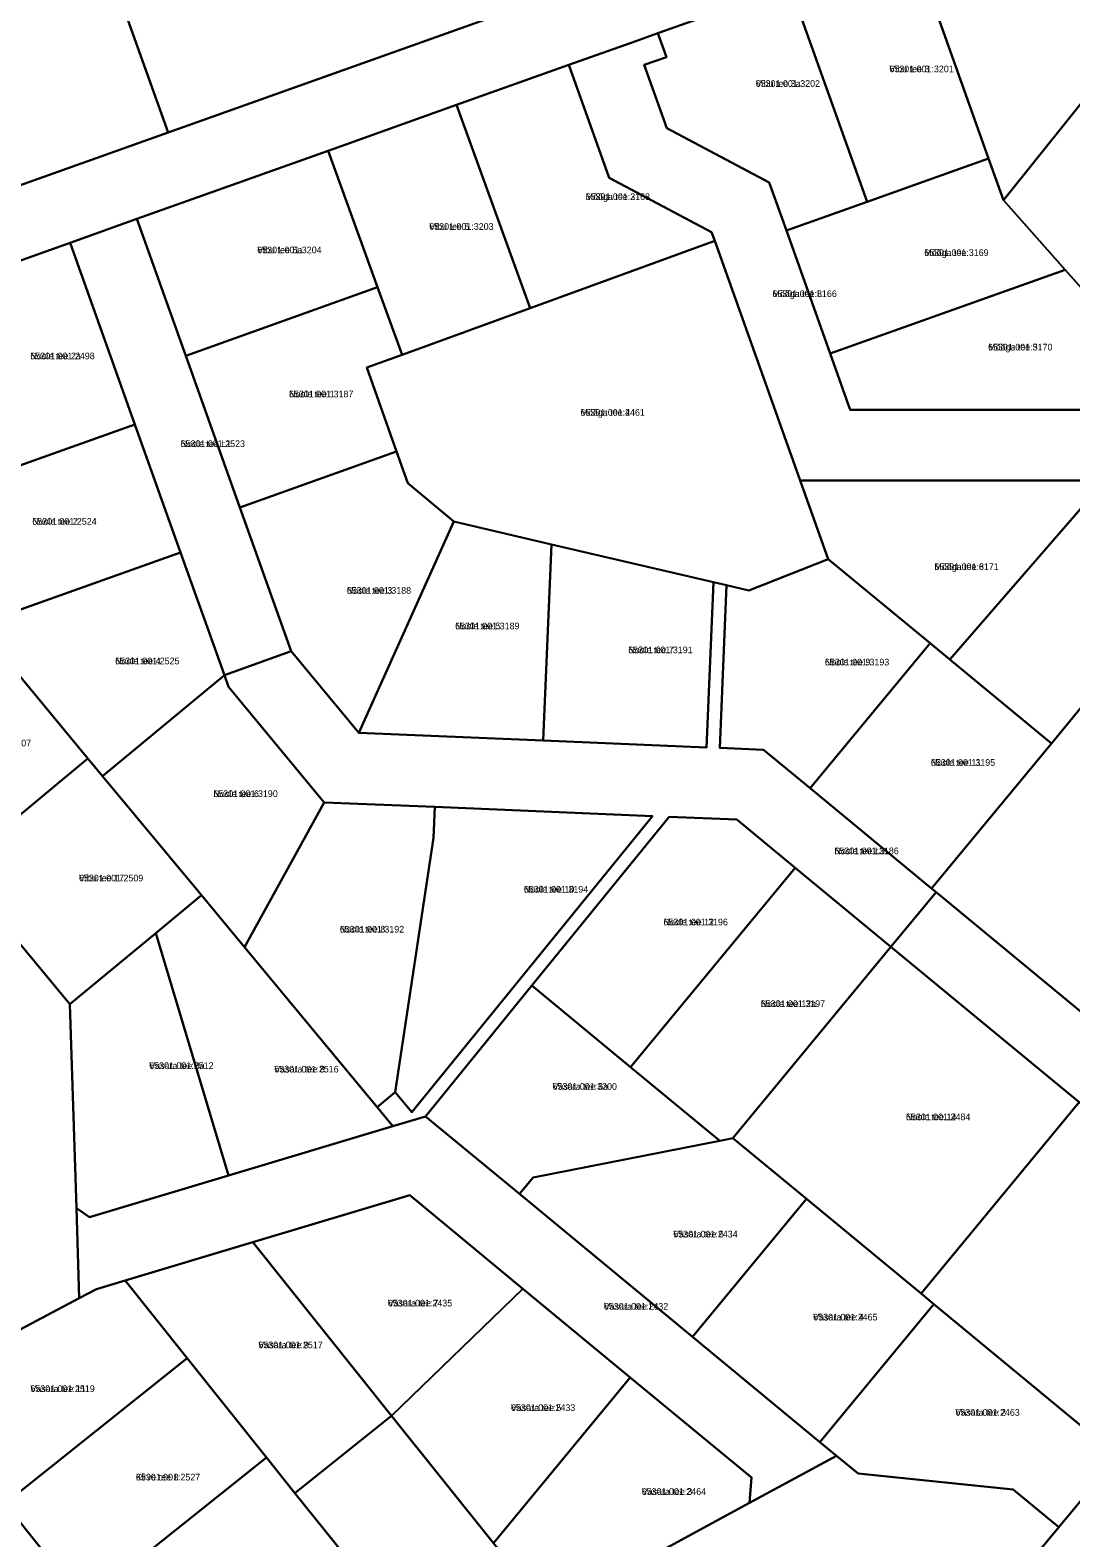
# Model space of a CAD drawing. Extents: x 543236 to 563717, y 6566033 to 6588992.
# Drawn here: x 546335.4 to 546570, y 6582727.8 to 6583067.8 of the extents above; entities that cross this region are included whole.
import ezdxf

# ---------------------------------------------------------------- set-up
doc = ezdxf.new("R2010")
doc.units = 0
for name, color, linetype in [('L_AADRESS', 7, 'Continuous'), ('PIIR', 7, 'Continuous'), ('TUNNUS', 7, 'Continuous')]:
    doc.layers.add(name, color=color, linetype=linetype)

msp = doc.modelspace()

# ---------------------------------------------------------------- linework, layer by layer
at = {"layer": 'PIIR'}
for points in [[(546592.18, 6583076.12), (546569.09, 6583101.29), (546579.76, 6583110.6), (546601.81, 6583088.17), (546654.4, 6583046.93), (546650.13, 6583042.2), (546634.72, 6583025.32), (546626.48, 6583016.25), (546596.15, 6582982.97), (546568.74, 6583013.76), (546554.83, 6583029.43)], [(546354.5, 6583078.41), (546379.75, 6583087.41), (546407.07, 6583097.15), (546433.62, 6583106.63), (546445.64, 6583072.93), (546366.52, 6583044.72)], [(546534.12, 6583087.49), (546566.53, 6583099.04), (546569.09, 6583101.29), (546592.18, 6583076.12), (546554.83, 6583029.43), (546551.45, 6583038.88)], [(546506.73, 6583077.72), (546534.12, 6583087.49), (546551.45, 6583038.88), (546524.06, 6583029.11)], [(546275.38, 6583050.2), (546297.81, 6583058.19), (546325.12, 6583067.92), (546352.44, 6583077.66), (546354.5, 6583078.41), (546366.52, 6583044.72), (546287.4, 6583016.51)], [(546476.92, 6583067.09), (546506.73, 6583077.72), (546524.06, 6583029.11), (546505.87, 6583022.63), (546502.02, 6583033.43), (546478.92, 6583045.71), (546473.85, 6583059.96), (546478.83, 6583061.73)], [(546456.84, 6583059.94), (546471.94, 6583065.32), (546476.92, 6583067.09), (546478.83, 6583061.73), (546473.85, 6583059.96), (546478.92, 6583045.71), (546502.02, 6583033.43), (546505.87, 6583022.63), (546515.78, 6582994.85), (546520.29, 6582982.2), (546583.47, 6582982.2), (546589.34, 6582977.35), (546609.88, 6582960.38), (546599.62, 6582948.1), (546577.72, 6582966.2), (546509.01, 6582966.2), (546489.73, 6583020.25), (546489.03, 6583022.22), (546465.95, 6583034.48)], [(546431.55, 6583050.92), (546456.84, 6583059.94), (546465.95, 6583034.48), (546489.03, 6583022.22), (546489.73, 6583020.25), (546448.16, 6583005.11)], [(546402.59, 6583040.59), (546431.55, 6583050.92), (546448.16, 6583005.11), (546419.27, 6582994.58), (546413.74, 6583009.83)], [(546359.49, 6583025.23), (546402.59, 6583040.59), (546413.74, 6583009.83), (546370.49, 6582994.37)], [(546505.87, 6583022.63), (546524.06, 6583029.11), (546551.45, 6583038.88), (546554.83, 6583029.43), (546568.74, 6583013.76), (546515.78, 6582994.85)], [(546344.42, 6583019.85), (546359.49, 6583025.23), (546370.49, 6582994.37), (546382.69, 6582960.16), (546394.26, 6582927.72), (546379.19, 6582922.34), (546369.33, 6582950), (546359.03, 6582978.88)], [(546311.88, 6583008.25), (546344.42, 6583019.85), (546359.03, 6582978.88), (546326.49, 6582967.28)], [(546411.32, 6582991.7), (546419.27, 6582994.58), (546448.16, 6583005.11), (546489.73, 6583020.25), (546509.01, 6582966.2), (546515.31, 6582948.52), (546497.41, 6582941.42), (546492.39, 6582942.6), (546489.42, 6582943.29), (546452.92, 6582951.83), (546430.89, 6582956.99), (546420.58, 6582965.63), (546418.03, 6582972.79)], [(546515.78, 6582994.85), (546568.74, 6583013.76), (546596.15, 6582982.97), (546589.34, 6582977.35), (546583.47, 6582982.2), (546520.29, 6582982.2)], [(546370.49, 6582994.37), (546413.74, 6583009.83), (546419.27, 6582994.58), (546411.32, 6582991.7), (546418.03, 6582972.79), (546382.69, 6582960.16)], [(546302.63, 6582958.77), (546326.49, 6582967.28), (546359.03, 6582978.88), (546369.33, 6582950), (546323.46, 6582933.65)], [(546382.69, 6582960.16), (546418.03, 6582972.79), (546420.58, 6582965.63), (546430.89, 6582956.99), (546409.5, 6582909.34), (546394.26, 6582927.72)], [(546509.01, 6582966.2), (546577.72, 6582966.2), (546542.69, 6582925.9), (546538.28, 6582929.54), (546515.31, 6582948.52)], [(546577.72, 6582966.2), (546599.62, 6582948.1), (546596.05, 6582943.78), (546572.2, 6582914.91), (546565.62, 6582906.95), (546542.69, 6582925.9)], [(546430.89, 6582956.99), (546452.92, 6582951.83), (546451.07, 6582907.6), (546409.5, 6582909.34)], [(546323.46, 6582933.65), (546369.33, 6582950), (546379.19, 6582922.34), (546351.73, 6582899.57), (546348.45, 6582903.53)], [(546452.92, 6582951.83), (546489.42, 6582943.29), (546487.86, 6582906.06), (546451.07, 6582907.6)], [(546492.39, 6582942.6), (546497.41, 6582941.42), (546515.31, 6582948.52), (546538.28, 6582929.54), (546511.26, 6582896.84), (546500.75, 6582905.52), (546490.85, 6582905.94)], [(546379.19, 6582922.34), (546394.26, 6582927.72), (546409.5, 6582909.34), (546451.07, 6582907.6), (546487.86, 6582906.06), (546489.42, 6582943.29), (546492.39, 6582942.6), (546490.85, 6582905.94), (546500.75, 6582905.52), (546511.26, 6582896.84), (546538.61, 6582874.25), (546539.65, 6582873.39), (546529.46, 6582861.05), (546507.86, 6582878.9), (546494.7, 6582889.76), (546479.46, 6582890.4), (546448.52, 6582852.34), (546424.54, 6582822.84), (546417.19, 6582820.63), (546413.64, 6582824.92), (546417.67, 6582828.31), (546421.45, 6582823.8), (546475.72, 6582890.56), (546426.67, 6582892.61), (546401.72, 6582893.66), (546380.14, 6582919.68)], [(546293.83, 6582909.07), (546323.46, 6582933.65), (546348.45, 6582903.53), (546318.81, 6582878.95)], [(546538.28, 6582929.54), (546542.69, 6582925.9), (546565.62, 6582906.95), (546538.61, 6582874.25), (546511.26, 6582896.84)], [(546351.73, 6582899.57), (546379.19, 6582922.34), (546380.14, 6582919.68), (546401.72, 6582893.66), (546383.74, 6582860.97), (546374.02, 6582872.69)], [(546572.2, 6582914.91), (546603.15, 6582889.34), (546616.11, 6582878.64), (546582.51, 6582837.98), (546582.05, 6582838.36), (546539.65, 6582873.39), (546538.61, 6582874.25), (546565.62, 6582906.95)], [(546318.81, 6582878.95), (546348.45, 6582903.53), (546351.73, 6582899.57), (546374.02, 6582872.69), (546363.72, 6582864.16), (546344.38, 6582848.12)], [(546401.72, 6582893.66), (546426.67, 6582892.61), (546426.37, 6582885.62), (546417.67, 6582828.31), (546413.64, 6582824.92), (546383.74, 6582860.97)], [(546426.67, 6582892.61), (546475.72, 6582890.56), (546421.45, 6582823.8), (546417.67, 6582828.31), (546426.37, 6582885.62)], [(546479.46, 6582890.4), (546494.7, 6582889.76), (546507.86, 6582878.9), (546470.74, 6582833.97), (546448.52, 6582852.34)], [(546507.86, 6582878.9), (546529.46, 6582861.05), (546493.83, 6582817.93), (546490.85, 6582817.34), (546470.74, 6582833.97)], [(546363.72, 6582864.16), (546374.02, 6582872.69), (546383.74, 6582860.97), (546413.64, 6582824.92), (546417.19, 6582820.63), (546380.14, 6582809.51)], [(546529.46, 6582861.05), (546539.65, 6582873.39), (546582.05, 6582838.36), (546626.94, 6582801.27), (546616.68, 6582788.99), (546571.86, 6582826.02)], [(546344.38, 6582848.12), (546363.72, 6582864.16), (546380.14, 6582809.51), (546348.79, 6582800.09), (546345.83, 6582802.18)], [(546493.83, 6582817.93), (546529.46, 6582861.05), (546571.86, 6582826.02), (546536.23, 6582782.9), (546510.39, 6582804.25)], [(546448.52, 6582852.34), (546470.74, 6582833.97), (546490.85, 6582817.34), (546448.79, 6582809.06), (546445.72, 6582805.34), (546424.54, 6582822.84)], [(546536.23, 6582782.9), (546571.86, 6582826.02), (546616.68, 6582788.99), (546580.62, 6582746.23), (546539.15, 6582780.49)], [(546345.83, 6582802.18), (546348.79, 6582800.09), (546380.14, 6582809.51), (546417.19, 6582820.63), (546424.54, 6582822.84), (546445.72, 6582805.34), (546484.69, 6582773.14), (546513.45, 6582749.39), (546517.18, 6582746.3), (546497.6, 6582735.66), (546498.02, 6582741.38), (546470.69, 6582763.95), (546446.44, 6582783.99), (546420.97, 6582805.04), (546385.64, 6582794.45), (546356.83, 6582785.82), (546350.39, 6582783.89), (546346.48, 6582781.82)], [(546445.72, 6582805.34), (546448.79, 6582809.06), (546490.85, 6582817.34), (546493.83, 6582817.93), (546510.39, 6582804.25), (546484.69, 6582773.14)], [(546385.64, 6582794.45), (546420.97, 6582805.04), (546446.44, 6582783.99), (546416.9, 6582755.32)], [(546484.69, 6582773.14), (546510.39, 6582804.25), (546536.23, 6582782.9), (546539.15, 6582780.49), (546513.45, 6582749.39)], [(546356.83, 6582785.82), (546385.64, 6582794.45), (546416.9, 6582755.32), (546395.1, 6582737.9), (546388.71, 6582745.9), (546370.8, 6582768.33)], [(546308.77, 6582761.86), (546346.48, 6582781.82), (546350.39, 6582783.89), (546356.83, 6582785.82), (546370.8, 6582768.33), (546329.78, 6582735.56)], [(546416.9, 6582755.32), (546446.44, 6582783.99), (546470.69, 6582763.95), (546439.84, 6582726.6)], [(546513.45, 6582749.39), (546539.15, 6582780.49), (546580.62, 6582746.23), (546567.28, 6582730.2), (546557, 6582738.69), (546522.04, 6582742.29), (546517.18, 6582746.3)], [(546329.78, 6582735.56), (546370.8, 6582768.33), (546388.71, 6582745.9), (546347.69, 6582713.14)], [(546439.84, 6582726.6), (546470.69, 6582763.95), (546498.02, 6582741.38), (546497.6, 6582735.66), (546452.29, 6582711.02)], [(546395.1, 6582737.9), (546416.9, 6582755.32), (546439.84, 6582726.6), (546452.29, 6582711.02), (546427.39, 6582697.48), (546406.56, 6582723.56)], [(546347.69, 6582713.14), (546388.71, 6582745.9), (546395.1, 6582737.9), (546406.56, 6582723.56), (546365.54, 6582690.79)]]:
    msp.add_lwpolyline(points, close=True, dxfattribs=at)
for points in [[(546506.73, 6583077.72), (546476.92, 6583067.09), (546471.94, 6583065.32), (546456.84, 6583059.94), (546431.55, 6583050.92), (546402.59, 6583040.59), (546359.49, 6583025.23), (546344.42, 6583019.85), (546311.88, 6583008.25)], [(546287.4, 6583016.51), (546366.52, 6583044.72), (546445.64, 6583072.93)], [(546318.81, 6582878.95), (546344.38, 6582848.12), (546345.83, 6582802.18), (546346.48, 6582781.82), (546308.77, 6582761.86)], [(546328.91, 6582711.01), (546310.19, 6582734.45), (546294.38, 6582754.24), (546308.77, 6582761.86), (546329.78, 6582735.56), (546347.69, 6582713.14)], [(546452.29, 6582711.02), (546497.6, 6582735.66), (546517.18, 6582746.3), (546522.04, 6582742.29), (546557, 6582738.69), (546567.28, 6582730.2), (546557.08, 6582717.86)], [(546584.34, 6582711.11), (546540.83, 6582687.7), (546525.43, 6582679.33), (546525.75, 6582679.77), (546557.08, 6582717.86), (546567.28, 6582730.2), (546580.62, 6582746.23)]]:
    msp.add_lwpolyline(points, dxfattribs=at)

# ---------------------------------------------------------------- texts
at = {"layer": 'L_AADRESS'}
for s, p in [('Vibu tee 3', (546529.09, 6583058.3)), ('Vibu tee 3a', (546498.96, 6583055)), ('Mõõga tee 2', (546460.64, 6583029.49)), ('Vibu tee 5', (546425.38, 6583022.76)), ('Vibu tee 5a', (546386.61, 6583017.48)), ('Mõõga tee 3', (546536.96, 6583016.87)), ('Mõõga tee L1', (546502.74, 6583007.6)), ('Noole tee 2a', (546335.46, 6582993.57)), ('Mõõga tee 5', (546551.35, 6582995.56)), ('Noole tee 1', (546393.77, 6582984.99)), ('Mõõga tee 4', (546459.48, 6582980.84)), ('Noole tee L1', (546369.34, 6582973.78)), ('Noole tee 2', (546335.9, 6582956.26)), ('Mõõga tee 6', (546539.25, 6582946.05)), ('Noole tee 3', (546406.79, 6582940.69)), ('Noole tee 5', (546431.21, 6582932.67)), ('Noole tee 4', (546354.57, 6582924.79)), ('Noole tee 7', (546470.25, 6582927.29)), ('Noole tee 9', (546514.57, 6582924.53)), ('Noole tee 11', (546538.44, 6582901.9)), ('Noole tee 6', (546376.72, 6582894.86)), ('Noole tee L3', (546516.71, 6582881.96)), ('Vibu tee 17', (546346.42, 6582875.83)), ('Noole tee 10', (546446.7, 6582873.31)), ('Noole tee 8', (546405.21, 6582864.3)), ('Noole tee 12', (546478.19, 6582865.91)), ('Noole tee 12a', (546500.1, 6582847.51)), ('Vasara tee 8a', (546362.26, 6582833.54)), ('Vasara tee 8', (546390.45, 6582832.74)), ('Vasara tee 6a', (546453.18, 6582828.84)), ('Noole tee 14', (546532.84, 6582821.98)), ('Vasara tee 6', (546480.39, 6582795.54)), ('Vasara tee 7', (546416.04, 6582779.98)), ('Vasara tee L1', (546464.74, 6582779.25)), ('Vasara tee 4', (546511.92, 6582776.82)), ('Vasara tee 9', (546386.86, 6582770.56)), ('Vasara tee 11', (546335.47, 6582760.69)), ('Vasara tee 5', (546443.79, 6582756.41)), ('Vasara tee 2', (546543.98, 6582755.34)), ('Kirve tee 8', (546359.25, 6582740.74)), ('Vasara tee 3', (546473.28, 6582737.49))]:
    msp.add_text(s, height=1.5, dxfattribs=at).set_placement(p)
at = {"layer": 'TUNNUS'}
for s, p in [('65301:001:3201', (546529.09, 6583058.3)), ('65301:001:3202', (546498.96, 6583055)), ('65301:001:3168', (546460.64, 6583029.49)), ('65301:001:3203', (546425.38, 6583022.76)), ('65301:001:3204', (546386.61, 6583017.48)), ('65301:001:3169', (546536.96, 6583016.87)), ('65301:001:3166', (546502.74, 6583007.6)), ('65301:001:2498', (546335.46, 6582993.57)), ('65301:001:3170', (546551.35, 6582995.56)), ('65301:001:3187', (546393.77, 6582984.99)), ('65301:001:2461', (546459.48, 6582980.84)), ('65301:001:2523', (546369.34, 6582973.78)), ('65301:001:2524', (546335.9, 6582956.26)), ('65301:001:3171', (546539.25, 6582946.05)), ('65301:001:3188', (546406.79, 6582940.69)), ('65301:001:3189', (546431.21, 6582932.67)), ('65301:001:2525', (546354.57, 6582924.79)), ('65301:001:3191', (546470.25, 6582927.29)), ('65301:001:3193', (546514.57, 6582924.53)), ('65301:001:2507', (546321.14, 6582906.3)), ('65301:001:3195', (546538.44, 6582901.9)), ('65301:001:3190', (546376.72, 6582894.86)), ('65301:001:3186', (546516.71, 6582881.96)), ('65301:001:2509', (546346.42, 6582875.83)), ('65301:001:3194', (546446.7, 6582873.31)), ('65301:001:3192', (546405.21, 6582864.3)), ('65301:001:3196', (546478.19, 6582865.91)), ('65301:001:3197', (546500.1, 6582847.51)), ('65301:001:2512', (546362.26, 6582833.54)), ('65301:001:2516', (546390.45, 6582832.74)), ('65301:001:3200', (546453.18, 6582828.84)), ('65301:001:2484', (546532.84, 6582821.98)), ('65301:001:2434', (546480.39, 6582795.54)), ('65301:001:2435', (546416.04, 6582779.98)), ('65301:001:2432', (546464.74, 6582779.25)), ('65301:001:2465', (546511.92, 6582776.82)), ('65301:001:2517', (546386.86, 6582770.56)), ('65301:001:2519', (546335.47, 6582760.69)), ('65301:001:2433', (546443.79, 6582756.41)), ('65301:001:2463', (546543.98, 6582755.34)), ('65301:001:2527', (546359.25, 6582740.74)), ('65301:001:2464', (546473.28, 6582737.49))]:
    msp.add_text(s, height=1.5, dxfattribs=at).set_placement(p)

doc.saveas('drawing.dxf')
